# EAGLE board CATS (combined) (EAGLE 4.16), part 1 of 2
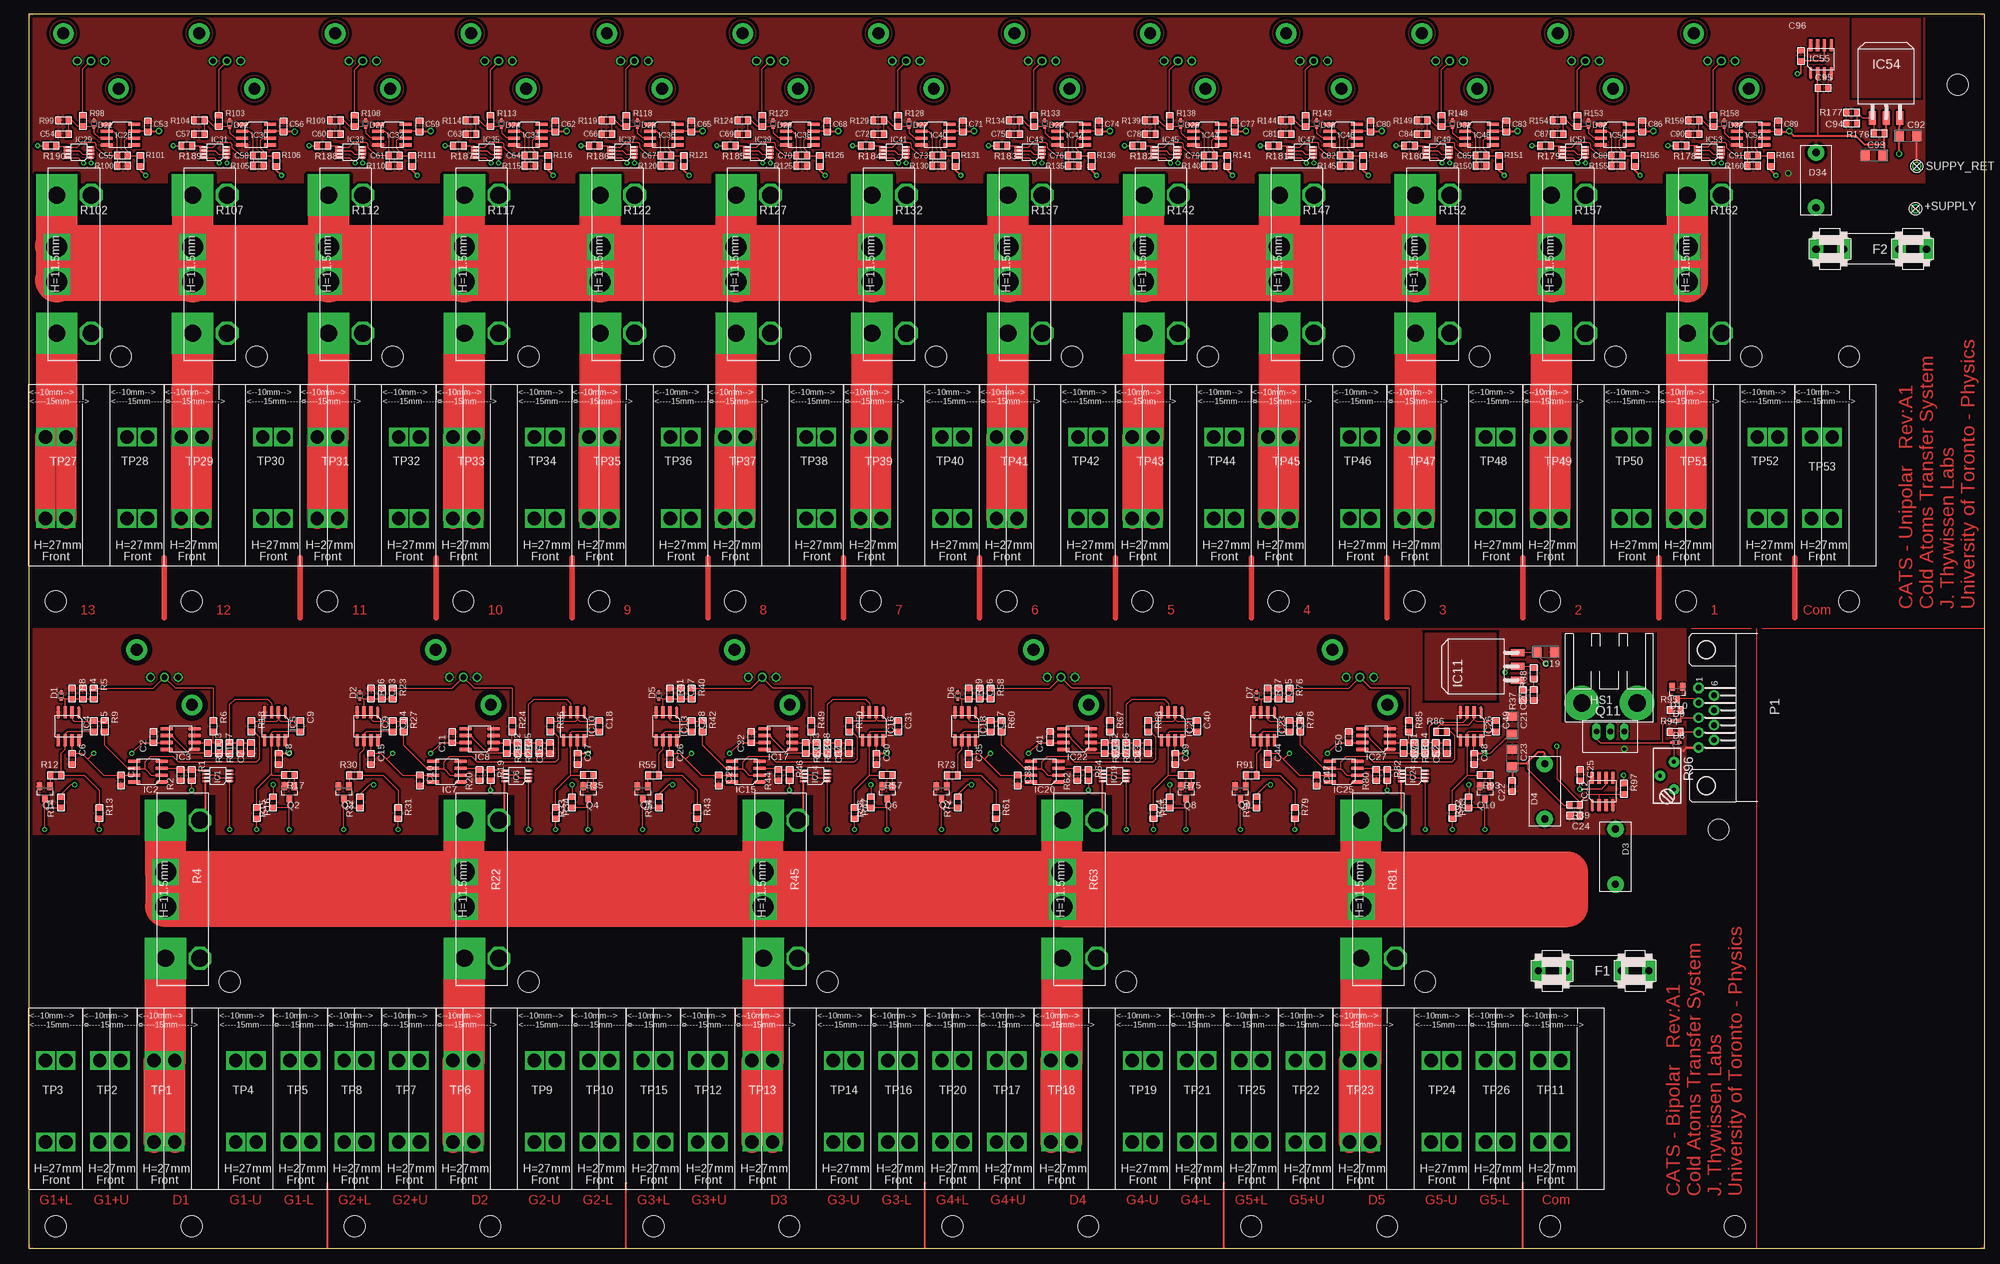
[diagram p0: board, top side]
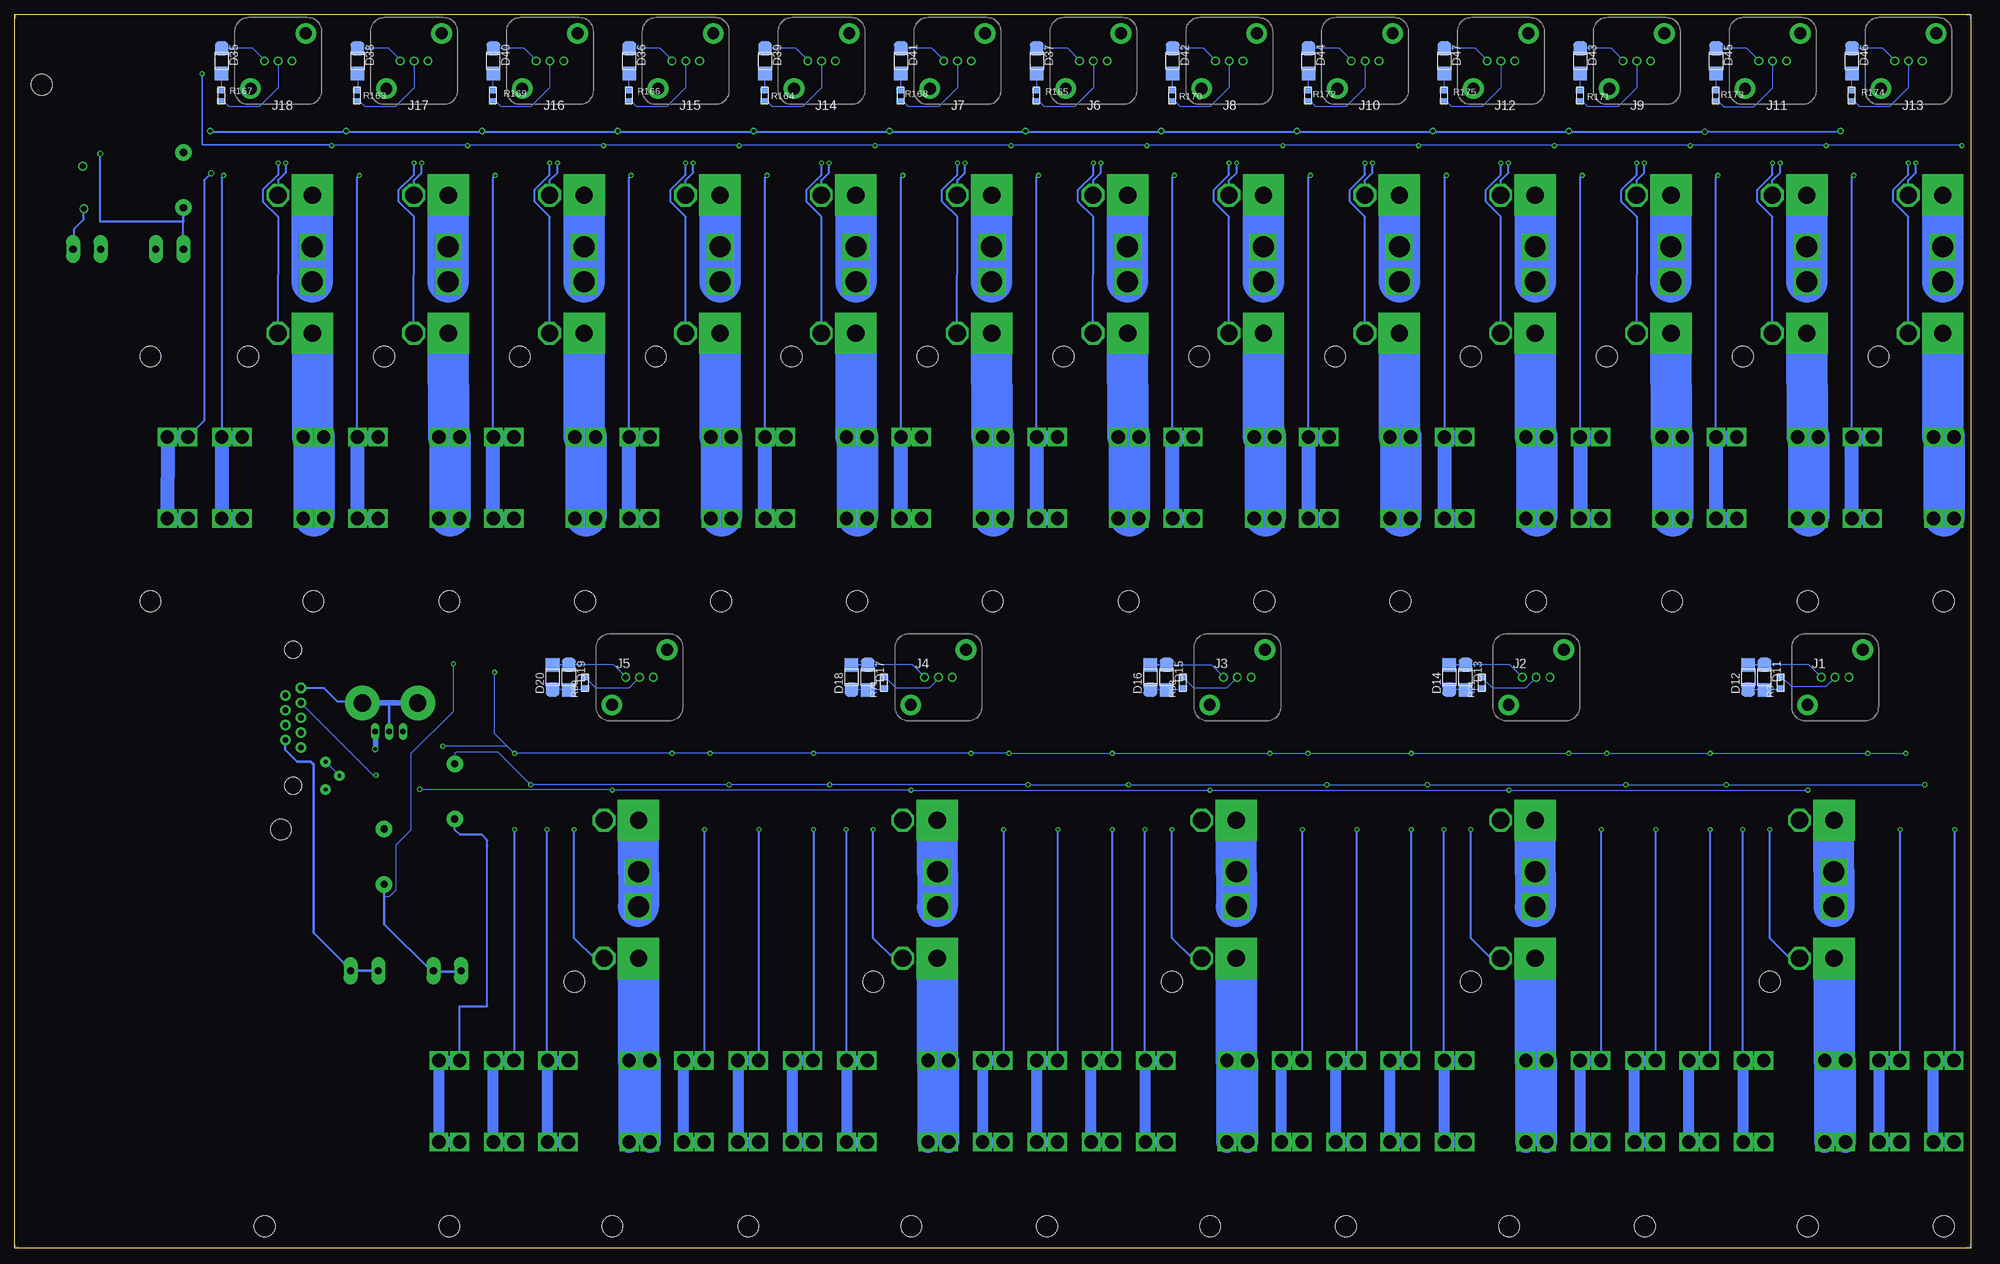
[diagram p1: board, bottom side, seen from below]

Size 360 x 227 mm. Coordinates in mm from the lower left corner, seen from the top.
Outline: 0,0 360,0 360,227 0,227 0,0
Copper layers (1*16): Top 0.035mm / dielectric 1.5mm / Bottom 0.035mm
Design rules "DRC standard check (7mil trace and gap, 20mil drill, etc)": minimum track width 7mil, minimum drill 20mil, track to track 7mil, track to pad 7mil, pad to pad 7mil, via to via 7mil, smd to smd 7mil, copper to edge 25mil, drill to drill 8mil, minimum pad ring 10mil, minimum via ring 8mil, stop-mask expansion 4mil, vias tented up to drill 0mil, thermal gap 10mil
Net classes: 0 default: clearance 0.406 mm; 1 Power: width 1.016 mm, drill 0.178 mm, clearance 3.175 mm
Holes 3.86 mm at 5,4 30,4 60,4 85,4 115,4 140,4 170,4 195,4 225,4 250,4 280,4 314,4 311,77 37,49 92,49 147,49 202,49 257,49 5,119 30,119 55,119 80,119 105,119 130,119 155,119 180,119 205,119 230,119 255,119 280,119 305,119 335,119 355,214 17,164 42,164 67,164 92,164 117,164 142,164 167,164 192,164 217,164 242,164 267,164 292,164 317,164 335,164
bKeepout: area 1.5,0.5 to 8.5,7.5; area 26.5,0.5 to 33.5,7.5; area 56.5,0.5 to 63.5,7.5; area 81.5,0.5 to 88.5,7.5; area 111.5,0.5 to 118.5,7.5; area 136.5,0.5 to 143.5,7.5; area 166.5,0.5 to 173.5,7.5; area 191.5,0.5 to 198.5,7.5; area 221.5,0.5 to 228.5,7.5; area 246.5,0.5 to 253.5,7.5; area 276.5,0.5 to 283.5,7.5; area 310.5,0.5 to 317.5,7.5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
tRestrict: 88 lines

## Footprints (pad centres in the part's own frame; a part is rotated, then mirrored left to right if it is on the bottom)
TP-0.042B = drill 1.067 round: TP 0,0
2012(0805) = smd 1.016 x 1.397: 1 -0.953,0; 2 0.953,0
EIA-A = smd 1.6 x 1.8: 1 -1.27,0; 2 1.905,0
SOD523 = smd 0.7 x 0.5: A 1.27,0; C 0,0
PASSIVE_0.4" = drill 1.321 pad 3.048 round: 1 -5.08,0; 2 5.08,0
SOT23 = smd 1 x 1.4: 1 -0.953,-0.953; 2 0.953,-0.953; 3 0,1.27
1209 = smd 2.5 x 2.5: A 2.3,0; K -2.3,0
FUSE = drill 1.321 pad 2.54 long: 1A -10.16,0; 1B -5.08,0; 2A 10.16,0; 2B 5.08,0
HEATSINK-5(TO-220) = drill 3.175 pad 6.35 round: 1 -5.08,0; 2 5.08,0
MSOP8 = smd 0.4 x 1.2: 1 -0.635,-1.905; 2 0,-1.905; 3 0.635,-1.905; 4 1.27,-1.905; 5 1.27,2.54; 6 0.635,2.54; 7 0,2.54; 8 -0.635,2.54
SOIC-8 = smd 0.6 x 2.2: 1 -1.27,-2.54; 2 0,-2.54; 3 1.27,-2.54; 4 2.54,-2.54; 5 2.54,2.54; 6 1.27,2.54; 7 0,2.54; 8 -1.27,2.54
TO263 = smd 1.27 x 2.54: 1 -2.54,0; 2 0,0; 3 2.54,0
CONN-BNC-AMP-TYPE1VERT = drill 1.067 round: CONDUCTOR 0,0; SHIELD1 -2.54,0; SHIELD2 2.54,0 | drill 2.184 pad 3.81 round: MTG1 -5.08,-5.08; MTG2 5.08,5.08
CONN-DB9-HORIZ1 = drill 1.067 pad 1.905 octagon: 1 -5.486,-1.422 | drill 1.067 pad 1.905 round: 2 -2.743,-1.422; 3 0,-1.422; 4 2.743,-1.422; 5 5.486,-1.422; 6 -4.115,1.422; 7 -1.372,1.422; 8 1.372,1.422; 9 4.115,1.422 | hole 3.175: -12.522,0; 12.522,0
TO220-VERTICAL = drill 1.067 long: 1 -2.54,0; 2 0,0; 3 2.54,0
OHMITE_650 = drill 3.175 pad 7.62 square: CURRENT1 -12.7,-3.81; CURRENT2 12.7,-3.81 | drill 3.175 octagon: SENSE1 -12.7,2.54; SENSE2 12.7,2.54
BOURNS-3296Y = drill 0.711 pad 1.905 round: CCW 2.54,1.27; CW -2.54,1.27; W 0,-1.27
PHEONIX_ZFKDS-10/15MM-TERMINAL-BLOCK = drill 2.438 square: T@1 -1.9,-7.5; T@2 1.9,-7.5; T@3 1.9,7.5; T@4 -1.9,7.5

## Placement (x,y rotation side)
+SUPPLY  [TP-0.042B]  347.25,191.2 90 top
C1  0.1uF  [2012(0805)]  17,86 270 top
C2  0.1uF  [2012(0805)]  23,94 90 top
C3  1nF  [2012(0805)]  33,92 270 top
C4  10nF  [2012(0805)]  10,102 270 top
C5  100pF  [2012(0805)]  12,96 270 top
C6  0.1uF  [2012(0805)]  8,90 270 top
C7  10nF  [2012(0805)]  41,92 90 top
C8  0.1uF  [2012(0805)]  46,90 270 top
C9  100pF  [2012(0805)]  50,96 270 top
C10  0.1uF  [2012(0805)]  72,86 270 top
C11  0.1uF  [2012(0805)]  78,94 90 top
C12  1nF  [2012(0805)]  88,92 270 top
C13  10nF  [2012(0805)]  65,102 270 top
C14  100pF  [2012(0805)]  67,96 270 top
C15  0.1uF  [2012(0805)]  63,90 270 top
C16  10nF  [2012(0805)]  96,92 90 top
C17  0.1uF  [2012(0805)]  101,90 270 top
C18  100pF  [2012(0805)]  105,96 270 top
C19  100uF/35V  [EIA-A]  279.5,109.65 180 top
C20  0.1uF  [2012(0805)]  277,101.75 90 top
C21  100uF/35V  [EIA-A]  273,96.5 270 top
C22  0.1uF  [2012(0805)]  273,85 90 top
C23  100uF/35V  [EIA-A]  273,90.5 270 top
C24  0.1uF  [2012(0805)]  284.5,79.5 180 top
C25  0.1uF  [2012(0805)]  285.5,87 270 top
C26  0.1uF  [2012(0805)]  118,90 270 top
C27  10nF  [2012(0805)]  120,102 270 top
C28  100pF  [2012(0805)]  122,96 270 top
C29  0.1uF  [2012(0805)]  127,86 270 top
C30  0.1uF  [2012(0805)]  156,90 270 top
C31  100pF  [2012(0805)]  160,96 270 top
C32  0.1uF  [2012(0805)]  133,94 90 top
C33  1nF  [2012(0805)]  143,92 270 top
C34  10nF  [2012(0805)]  151,92 90 top
C35  0.1uF  [2012(0805)]  173,90 270 top
C36  10nF  [2012(0805)]  175,102 270 top
C37  100pF  [2012(0805)]  177,96 270 top
C38  0.1uF  [2012(0805)]  182,86 270 top
C39  0.1uF  [2012(0805)]  211,90 270 top
C40  100pF  [2012(0805)]  215,96 270 top
C41  0.1uF  [2012(0805)]  188,94 90 top
C42  1nF  [2012(0805)]  198,92 270 top
C43  10nF  [2012(0805)]  206,92 90 top
C44  0.1uF  [2012(0805)]  228,90 270 top
C45  10nF  [2012(0805)]  230,102 270 top
C46  100pF  [2012(0805)]  232,96 270 top
C47  0.1uF  [2012(0805)]  237,86 270 top
C48  0.1uF  [2012(0805)]  266,90 270 top
C49  100pF  [2012(0805)]  270,96 270 top
C50  0.1uF  [2012(0805)]  243,94 90 top
C51  1nF  [2012(0805)]  253,92 270 top
C52  10nF  [2012(0805)]  261,92 90 top
C53  0.1uF  [2012(0805)]  21.97,206.35 90 top
C54  10nF  [2012(0805)]  6.43,204.95 0 top
C55  100pF  [2012(0805)]  17.27,201.01 0 top
C56  0.1uF  [2012(0805)]  46.97,206.35 90 top
C57  10nF  [2012(0805)]  31.43,204.95 0 top
C58  100pF  [2012(0805)]  42.27,201.01 0 top
C59  0.1uF  [2012(0805)]  71.97,206.35 90 top
C60  10nF  [2012(0805)]  56.43,204.95 0 top
C61  100pF  [2012(0805)]  67.27,201.01 0 top
C62  0.1uF  [2012(0805)]  96.97,206.35 90 top
C63  10nF  [2012(0805)]  81.43,204.95 0 top
C64  100pF  [2012(0805)]  92.27,201.01 0 top
C65  0.1uF  [2012(0805)]  121.97,206.35 90 top
C66  10nF  [2012(0805)]  106.43,204.95 0 top
C67  100pF  [2012(0805)]  117.27,201.01 0 top
C68  0.1uF  [2012(0805)]  146.97,206.35 90 top
C69  10nF  [2012(0805)]  131.43,204.95 0 top
C70  100pF  [2012(0805)]  142.27,201.01 0 top
C71  0.1uF  [2012(0805)]  171.97,206.35 90 top
C72  10nF  [2012(0805)]  156.43,204.95 0 top
C73  100pF  [2012(0805)]  167.27,201.01 0 top
C74  0.1uF  [2012(0805)]  196.97,206.35 90 top
C75  10nF  [2012(0805)]  181.43,204.95 0 top
C76  100pF  [2012(0805)]  192.27,201.01 0 top
C77  0.1uF  [2012(0805)]  221.97,206.35 90 top
C78  10nF  [2012(0805)]  206.43,204.95 0 top
C79  100pF  [2012(0805)]  217.27,201.01 0 top
C80  0.1uF  [2012(0805)]  246.97,206.35 90 top
C81  10nF  [2012(0805)]  231.43,204.95 0 top
C82  100pF  [2012(0805)]  242.27,201.01 0 top
C83  0.1uF  [2012(0805)]  271.97,206.35 90 top
C84  10nF  [2012(0805)]  256.43,204.95 0 top
C85  100pF  [2012(0805)]  267.27,201.01 0 top
C86  0.1uF  [2012(0805)]  296.97,206.35 90 top
C87  10nF  [2012(0805)]  281.43,204.95 0 top
C88  100pF  [2012(0805)]  292.27,201.01 0 top
C89  0.1uF  [2012(0805)]  321.97,206.35 90 top
C90  10nF  [2012(0805)]  306.43,204.95 0 top
C91  100pF  [2012(0805)]  317.27,201.01 0 top
C92  100uF/35V  [EIA-A]  346.14,204.6 180 top
C93  100uF/35V  [EIA-A]  339.28,201.04 0 top
C94  0.1uF  [2012(0805)]  335.47,206.88 0 top
C95  0.1uF  [2012(0805)]  330.22,213.42 0 top
C96  0.1uF  [2012(0805)]  326.14,219.33 270 top
D1  1N4148WT  [SOD523]  6,101 90 top
D2  1N4148WT  [SOD523]  61,101 90 top
D3  1N4750A  [PASSIVE_0.4"]  292,72 270 top
D4  1N4740A  [PASSIVE_0.4"]  279,84 90 top
D5  1N4148WT  [SOD523]  116,101 90 top
D6  1N4148WT  [SOD523]  171,101 90 top
D7  1N4148WT  [SOD523]  226,101 90 top
D8  1N4148WT  [SOD523]  302.5,93 0 top
D9  1N4148WT  [SOD523]  302.5,97 0 top
D10  BZX84-C5V1  [SOT23]  303.4,102.3 180 top
D11  SML-LXL1209UPGC  [1209]  38,105 270 bottom
D12  SML-LXL1209SOC  [1209]  41,105 90 bottom
D13  SML-LXL1209UPGC  [1209]  93,105 270 bottom
D14  SML-LXL1209SOC  [1209]  96,105 90 bottom
D15  SML-LXL1209UPGC  [1209]  148,105 270 bottom
D16  SML-LXL1209SOC  [1209]  151,105 90 bottom
D17  SML-LXL1209UPGC  [1209]  203,105 270 bottom
D18  SML-LXL1209SOC  [1209]  206,105 90 bottom
D19  SML-LXL1209UPGC  [1209]  258,105 270 bottom
D20  SML-LXL1209SOC  [1209]  261,105 90 bottom
D21  1N4148WT  [SOD523]  12.02,206.22 90 top
D22  1N4148WT  [SOD523]  37.02,206.22 90 top
D23  1N4148WT  [SOD523]  62.02,206.22 90 top
D24  1N4148WT  [SOD523]  87.02,206.22 90 top
D25  1N4148WT  [SOD523]  112.02,206.22 90 top
D26  1N4148WT  [SOD523]  137.02,206.22 90 top
D27  1N4148WT  [SOD523]  162.02,206.22 90 top
D28  1N4148WT  [SOD523]  187.02,206.22 90 top
D29  1N4148WT  [SOD523]  212.02,206.22 90 top
D30  1N4148WT  [SOD523]  237.02,206.22 90 top
D31  1N4148WT  [SOD523]  262.02,206.22 90 top
D32  1N4148WT  [SOD523]  287.02,206.22 90 top
D33  1N4148WT  [SOD523]  312.02,206.22 90 top
D34  1N4750A  [PASSIVE_0.4"]  328.93,196.47 270 top
D35  SML-LXL1209UPGC  [1209]  321.9,218.4 270 bottom
D36  SML-LXL1209UPGC  [1209]  246.9,218.4 270 bottom
D37  SML-LXL1209UPGC  [1209]  171.9,218.4 270 bottom
D38  SML-LXL1209UPGC  [1209]  296.9,218.4 270 bottom
D39  SML-LXL1209UPGC  [1209]  221.9,218.4 270 bottom
D40  SML-LXL1209UPGC  [1209]  271.9,218.4 270 bottom
D41  SML-LXL1209UPGC  [1209]  196.9,218.4 270 bottom
D42  SML-LXL1209UPGC  [1209]  146.9,218.4 270 bottom
D43  SML-LXL1209UPGC  [1209]  71.9,218.4 270 bottom
D44  SML-LXL1209UPGC  [1209]  121.9,218.4 270 bottom
D45  SML-LXL1209UPGC  [1209]  46.9,218.4 270 bottom
D46  SML-LXL1209UPGC  [1209]  21.9,218.4 270 bottom
D47  SML-LXL1209UPGC  [1209]  96.9,218.4 270 bottom
F1  0.1A-5x20  [FUSE]  288,51 180 top
F2  0.1A-5x20  [FUSE]  339.09,183.77 180 top
HS1  634-20ABP  [HEATSINK-5(TO-220)]  290.89,100.28 0 top
IC1  AD8212RMZ  [MSOP8]  35.15,86.54 90 top
IC2  AD820ARZ  [SOIC-8]  22,87 90 top
IC3  AD820ARZ  [SOIC-8]  28,93 90 top
IC4  AD820ARZ  [SOIC-8]  8,96 180 top
IC5  AD820ARZ  [SOIC-8]  46,96 180 top
IC6  AD8212RMZ  [MSOP8]  90.15,86.54 90 top
IC7  AD820ARZ  [SOIC-8]  77,87 90 top
IC8  AD820ARZ  [SOIC-8]  83,93 90 top
IC9  AD820ARZ  [SOIC-8]  63,96 180 top
IC10  AD820ARZ  [SOIC-8]  101,96 180 top
IC11  LM1086CS-ADJ  [TO263]  274,107 90 top
IC12  ADR435AR(Z)  [SOIC-8]  289,84 0 top
IC13  AD820ARZ  [SOIC-8]  118,96 180 top
IC14  AD8212RMZ  [MSOP8]  145.15,86.54 90 top
IC15  AD820ARZ  [SOIC-8]  132,87 90 top
IC16  AD820ARZ  [SOIC-8]  156,96 180 top
IC17  AD820ARZ  [SOIC-8]  138,93 90 top
IC18  AD820ARZ  [SOIC-8]  173,96 180 top
IC19  AD8212RMZ  [MSOP8]  200.15,86.54 90 top
IC20  AD820ARZ  [SOIC-8]  187,87 90 top
IC21  AD820ARZ  [SOIC-8]  211,96 180 top
IC22  AD820ARZ  [SOIC-8]  193,93 90 top
IC23  AD820ARZ  [SOIC-8]  228,96 180 top
IC24  AD8212RMZ  [MSOP8]  255.15,86.54 90 top
IC25  AD820ARZ  [SOIC-8]  242,87 90 top
IC26  AD820ARZ  [SOIC-8]  266,96 180 top
IC27  AD820ARZ  [SOIC-8]  248,93 90 top
IC28  AD820ARZ  [SOIC-8]  16.89,205.46 270 top
IC29  AD8212RMZ  [MSOP8]  9.61,201.27 90 top
IC30  AD820ARZ  [SOIC-8]  41.89,205.46 270 top
IC31  AD8212RMZ  [MSOP8]  34.6,201.27 90 top
IC32  AD820ARZ  [SOIC-8]  66.89,205.46 270 top
IC33  AD8212RMZ  [MSOP8]  59.6,201.27 90 top
IC34  AD820ARZ  [SOIC-8]  91.89,205.46 270 top
IC35  AD8212RMZ  [MSOP8]  84.61,201.27 90 top
IC36  AD820ARZ  [SOIC-8]  116.89,205.46 270 top
IC37  AD8212RMZ  [MSOP8]  109.61,201.27 90 top
IC38  AD820ARZ  [SOIC-8]  141.89,205.46 270 top
IC39  AD8212RMZ  [MSOP8]  134.6,201.27 90 top
IC40  AD820ARZ  [SOIC-8]  166.89,205.46 270 top
IC41  AD8212RMZ  [MSOP8]  159.6,201.27 90 top
IC42  AD820ARZ  [SOIC-8]  191.89,205.46 270 top
IC43  AD8212RMZ  [MSOP8]  184.6,201.27 90 top
IC44  AD820ARZ  [SOIC-8]  216.89,205.46 270 top
IC45  AD8212RMZ  [MSOP8]  209.6,201.27 90 top
IC46  AD820ARZ  [SOIC-8]  241.89,205.46 270 top
IC47  AD8212RMZ  [MSOP8]  234.6,201.27 90 top
IC48  AD820ARZ  [SOIC-8]  266.89,205.46 270 top
IC49  AD8212RMZ  [MSOP8]  259.61,201.27 90 top
IC50  AD820ARZ  [SOIC-8]  291.89,205.46 270 top
IC51  AD8212RMZ  [MSOP8]  284.61,201.27 90 top
IC52  AD820ARZ  [SOIC-8]  316.89,205.46 270 top
IC53  AD8212RMZ  [MSOP8]  309.61,201.27 90 top
IC54  LM1086CS-ADJ  [TO263]  341.82,207.9 0 top
IC55  ADR435AR(Z)  [SOIC-8]  329.18,218.69 0 top
J1  Amp 227673-1  [CONN-BNC-AMP-TYPE1VERT]  25,105 0 bottom
J2  Amp 227673-1  [CONN-BNC-AMP-TYPE1VERT]  80,105 0 bottom
J3  Amp 227673-1  [CONN-BNC-AMP-TYPE1VERT]  135,105 0 bottom
J4  Amp 227673-1  [CONN-BNC-AMP-TYPE1VERT]  190,105 0 bottom
J5  Amp 227673-1  [CONN-BNC-AMP-TYPE1VERT]  245,105 0 bottom
J6  Amp 227673-1  [CONN-BNC-AMP-TYPE1VERT]  161.49,218.38 0 bottom
J7  Amp 227673-1  [CONN-BNC-AMP-TYPE1VERT]  186.49,218.38 0 bottom
J8  Amp 227673-1  [CONN-BNC-AMP-TYPE1VERT]  136.49,218.38 0 bottom
J9  Amp 227673-1  [CONN-BNC-AMP-TYPE1VERT]  61.49,218.38 0 bottom
J10  Amp 227673-1  [CONN-BNC-AMP-TYPE1VERT]  111.49,218.38 0 bottom
J11  Amp 227673-1  [CONN-BNC-AMP-TYPE1VERT]  36.49,218.38 0 bottom
J12  Amp 227673-1  [CONN-BNC-AMP-TYPE1VERT]  86.49,218.38 0 bottom
J13  Amp 227673-1  [CONN-BNC-AMP-TYPE1VERT]  11.49,218.38 0 bottom
J14  Amp 227673-1  [CONN-BNC-AMP-TYPE1VERT]  211.49,218.38 0 bottom
J15  Amp 227673-1  [CONN-BNC-AMP-TYPE1VERT]  236.49,218.38 0 bottom
J16  Amp 227673-1  [CONN-BNC-AMP-TYPE1VERT]  261.49,218.38 0 bottom
J17  Amp 227673-1  [CONN-BNC-AMP-TYPE1VERT]  286.49,218.38 0 bottom
J18  Amp 227673-1  [CONN-BNC-AMP-TYPE1VERT]  311.49,218.38 0 bottom
P1  [CONN-DB9-HORIZ1]  308.74,97.57 270 top
Q1  MMBT5551  [SOT23]  3,84 180 top
Q2  MMBT5551  [SOT23]  48,84 180 top
Q3  MMBT5551  [SOT23]  58,84 180 top
Q4  MMBT5551  [SOT23]  103,84 180 top
Q5  MMBT5551  [SOT23]  113,84 180 top
Q6  MMBT5551  [SOT23]  158,84 180 top
Q7  MMBT5551  [SOT23]  168,84 180 top
Q8  MMBT5551  [SOT23]  213,84 180 top
Q9  MMBT5551  [SOT23]  223,84 180 top
Q10  MMBT5551  [SOT23]  268,84 180 top
Q11  NDP6060L  [TO220-VERTICAL]  291.08,95.04 0 top
R1  75K  [2012(0805)]  30,87 270 top
R2  3.92K  [2012(0805)]  28,87 90 top
R3  3.01K  [2012(0805)]  35,104 90 bottom
R4  2mOhm/5W  [OHMITE_650]  29,66 270 top
R5  9.09K  [2012(0805)]  12,102 270 top
R6  10K  [2012(0805)]  34,96 270 top
R7  10K  [2012(0805)]  35,92 270 top
R8  1K  [2012(0805)]  8,102 270 top
R9  3.92K  [2012(0805)]  14,96 270 top
R10  9.09K  [2012(0805)]  37,92 90 top
R11  1K  [2012(0805)]  39,92 90 top
R12  10K  [2012(0805)]  5,87 0 top
R13  100  [2012(0805)]  13,80 270 top
R14  2K  [2012(0805)]  6,82 90 top
R15  2K  [2012(0805)]  45,82 90 top
R16  100  [2012(0805)]  42,80 270 top
R17  10K  [2012(0805)]  48,87 180 top
R18  3.92K  [2012(0805)]  41,96 270 top
R19  75K  [2012(0805)]  85,87 270 top
R20  3.92K  [2012(0805)]  83,87 90 top
R21  3.01K  [2012(0805)]  90,104 90 bottom
R22  2mOhm/5W  [OHMITE_650]  84,66 270 top
R23  9.09K  [2012(0805)]  67,102 270 top
R24  10K  [2012(0805)]  89,96 270 top
R25  10K  [2012(0805)]  90,92 270 top
R26  1K  [2012(0805)]  63,102 270 top
R27  3.92K  [2012(0805)]  69,96 270 top
R28  9.09K  [2012(0805)]  92,92 90 top
R29  1K  [2012(0805)]  94,92 90 top
R30  10K  [2012(0805)]  60,87 0 top
R31  100  [2012(0805)]  68,80 270 top
R32  2K  [2012(0805)]  61,82 90 top
R33  2K  [2012(0805)]  100,82 90 top
R34  100  [2012(0805)]  97,80 270 top
R35  10K  [2012(0805)]  103,87 180 top
R36  3.92K  [2012(0805)]  96,96 270 top
R37  1.47K  [2012(0805)]  275,101.75 90 top
R38  124  [2012(0805)]  277,105.75 90 top
R39  301  [2012(0805)]  284.5,81.5 180 top
R40  9.09K  [2012(0805)]  122,102 270 top
R41  1K  [2012(0805)]  118,102 270 top
R42  3.92K  [2012(0805)]  124,96 270 top
R43  100  [2012(0805)]  123,80 270 top
R44  3.92K  [2012(0805)]  138,87 90 top
R45  2mOhm/5W  [OHMITE_650]  139,66 270 top
R46  75K  [2012(0805)]  140,87 270 top
R47  100  [2012(0805)]  152,80 270 top
R48  10K  [2012(0805)]  145,92 270 top
R49  10K  [2012(0805)]  144,96 270 top
R50  3.92K  [2012(0805)]  151,96 270 top
R51  9.09K  [2012(0805)]  147,92 90 top
R52  1K  [2012(0805)]  149,92 90 top
R53  3.01K  [2012(0805)]  145,104 90 bottom
R54  2K  [2012(0805)]  116,82 90 top
R55  10K  [2012(0805)]  115,87 0 top
R56  2K  [2012(0805)]  155,82 90 top
R57  10K  [2012(0805)]  158,87 180 top
R58  9.09K  [2012(0805)]  177,102 270 top
R59  1K  [2012(0805)]  173,102 270 top
R60  3.92K  [2012(0805)]  179,96 270 top
R61  100  [2012(0805)]  178,80 270 top
R62  3.92K  [2012(0805)]  193,87 90 top
R63  2mOhm/5W  [OHMITE_650]  194,66 270 top
R64  75K  [2012(0805)]  195,87 270 top
R65  100  [2012(0805)]  207,80 270 top
R66  10K  [2012(0805)]  200,92 270 top
R67  10K  [2012(0805)]  199,96 270 top
R68  3.92K  [2012(0805)]  206,96 270 top
R69  9.09K  [2012(0805)]  202,92 90 top
R70  1K  [2012(0805)]  204,92 90 top
R71  3.01K  [2012(0805)]  200,104 90 bottom
R72  2K  [2012(0805)]  171,82 90 top
R73  10K  [2012(0805)]  170,87 0 top
R74  2K  [2012(0805)]  210,82 90 top
R75  10K  [2012(0805)]  213,87 180 top
R76  9.09K  [2012(0805)]  232,102 270 top
R77  1K  [2012(0805)]  228,102 270 top
R78  3.92K  [2012(0805)]  234,96 270 top
R79  100  [2012(0805)]  233,80 270 top
R80  3.92K  [2012(0805)]  248,87 90 top
R81  2mOhm/5W  [OHMITE_650]  249,66 270 top
R82  75K  [2012(0805)]  250,87 270 top
R83  100  [2012(0805)]  262,80 270 top
R84  10K  [2012(0805)]  255,92 270 top
R85  10K  [2012(0805)]  254,96 270 top
R86  3.92K  [2012(0805)]  260,95 0 top
R87  9.09K  [2012(0805)]  257,92 90 top
R88  1K  [2012(0805)]  259,92 90 top
R89  3.01K  [2012(0805)]  255,104 90 bottom
R90  2K  [2012(0805)]  226,82 90 top
R91  10K  [2012(0805)]  225,87 0 top
R92  2K  [2012(0805)]  265,82 90 top
R93  10K  [2012(0805)]  268,87 180 top
R94  ???  [2012(0805)]  303,95 0 top
R95  ???  [2012(0805)]  303,99 0 top
R96  3296Y-10K  [BOURNS-3296Y]  301.5,86.9 270 top
R97  1K  [2012(0805)]  293.55,84.5 270 top
R98  9.09K  [2012(0805)]  9.99,207.36 270 top
R99  1K  [2012(0805)]  6.43,207.49 0 top
R100  3.92K  [2012(0805)]  17.27,199.11 180 top
R101  100  [2012(0805)]  20.57,200 270 top
R102  2mOhm/5W  [OHMITE_650]  9,181 270 top
R103  9.09K  [2012(0805)]  34.99,207.36 270 top
R104  1K  [2012(0805)]  31.43,207.49 0 top
R105  3.92K  [2012(0805)]  42.27,199.11 180 top
R106  100  [2012(0805)]  45.57,200 270 top
R107  2mOhm/5W  [OHMITE_650]  34,181 270 top
R108  9.09K  [2012(0805)]  59.99,207.36 270 top
R109  1K  [2012(0805)]  56.43,207.49 0 top
R110  3.92K  [2012(0805)]  67.27,199.11 180 top
R111  100  [2012(0805)]  70.57,200 270 top
R112  2mOhm/5W  [OHMITE_650]  59,181 270 top
R113  9.09K  [2012(0805)]  84.99,207.36 270 top
R114  1K  [2012(0805)]  81.43,207.49 0 top
R115  3.92K  [2012(0805)]  92.27,199.11 180 top
R116  100  [2012(0805)]  95.57,200 270 top
R117  2mOhm/5W  [OHMITE_650]  84,181 270 top
R118  9.09K  [2012(0805)]  109.99,207.36 270 top
R119  1K  [2012(0805)]  106.43,207.49 0 top
R120  3.92K  [2012(0805)]  117.27,199.11 180 top
R121  100  [2012(0805)]  120.57,200 270 top
R122  2mOhm/5W  [OHMITE_650]  109,181 270 top
R123  9.09K  [2012(0805)]  134.99,207.36 270 top
R124  1K  [2012(0805)]  131.43,207.49 0 top
R125  3.92K  [2012(0805)]  142.27,199.11 180 top
R126  100  [2012(0805)]  145.57,200 270 top
R127  2mOhm/5W  [OHMITE_650]  134,181 270 top
R128  9.09K  [2012(0805)]  159.99,207.36 270 top
R129  1K  [2012(0805)]  156.43,207.49 0 top
R130  3.92K  [2012(0805)]  167.27,199.11 180 top
R131  100  [2012(0805)]  170.57,200 270 top
R132  2mOhm/5W  [OHMITE_650]  159,181 270 top
R133  9.09K  [2012(0805)]  184.99,207.36 270 top
R134  1K  [2012(0805)]  181.43,207.49 0 top
R135  3.92K  [2012(0805)]  192.27,199.11 180 top
R136  100  [2012(0805)]  195.57,200 270 top
R137  2mOhm/5W  [OHMITE_650]  184,181 270 top
R138  9.09K  [2012(0805)]  209.99,207.36 270 top
R139  1K  [2012(0805)]  206.43,207.49 0 top
R140  3.92K  [2012(0805)]  217.27,199.11 180 top
R141  100  [2012(0805)]  220.57,200 270 top
R142  2mOhm/5W  [OHMITE_650]  209,181 270 top
R143  9.09K  [2012(0805)]  234.99,207.36 270 top
R144  1K  [2012(0805)]  231.43,207.49 0 top
R145  3.92K  [2012(0805)]  242.27,199.11 180 top
R146  100  [2012(0805)]  245.57,200 270 top
R147  2mOhm/5W  [OHMITE_650]  234,181 270 top
R148  9.09K  [2012(0805)]  259.99,207.36 270 top
R149  1K  [2012(0805)]  256.43,207.49 0 top
R150  3.92K  [2012(0805)]  267.27,199.11 180 top
R151  100  [2012(0805)]  270.57,200 270 top
R152  2mOhm/5W  [OHMITE_650]  259,181 270 top
R153  9.09K  [2012(0805)]  284.99,207.36 270 top
R154  1K  [2012(0805)]  281.43,207.49 0 top
R155  3.92K  [2012(0805)]  292.27,199.11 180 top
R156  100  [2012(0805)]  295.57,200 270 top
R157  2mOhm/5W  [OHMITE_650]  284,181 270 top
R158  9.09K  [2012(0805)]  309.99,207.36 270 top
R159  1K  [2012(0805)]  306.43,207.49 0 top
R160  3.92K  [2012(0805)]  317.27,199.11 180 top
R161  100  [2012(0805)]  320.57,200 270 top
R162  2mOhm/5W  [OHMITE_650]  309,181 270 top
R163  3.01K  [2012(0805)]  297,212 270 bottom
R164  3.01K  [2012(0805)]  222,212 270 bottom
R165  3.01K  [2012(0805)]  172,212 270 bottom
R166  3.01K  [2012(0805)]  247,212 270 bottom
R167  3.01K  [2012(0805)]  322,212 270 bottom
R168  3.01K  [2012(0805)]  197,212 270 bottom
R169  3.01K  [2012(0805)]  272,212 270 bottom
R170  3.01K  [2012(0805)]  147,212 270 bottom
R171  3.01K  [2012(0805)]  72,212 270 bottom
R172  3.01K  [2012(0805)]  122,212 270 bottom
R173  3.01K  [2012(0805)]  47,212 270 bottom
R174  3.01K  [2012(0805)]  22,212 270 bottom
R175  3.01K  [2012(0805)]  97,212 270 bottom
R176  124  [2012(0805)]  340.55,205.11 0 top
R177  1.47K  [2012(0805)]  335.47,208.92 0 top
R178  75K  [2012(0805)]  304.12,202.76 180 top
R179  75K  [2012(0805)]  279.12,202.76 180 top
R180  75K  [2012(0805)]  254.12,202.76 180 top
R181  75K  [2012(0805)]  229.12,202.76 180 top
R182  75K  [2012(0805)]  204.12,202.76 180 top
R183  75K  [2012(0805)]  179.12,202.76 180 top
R184  75K  [2012(0805)]  154.12,202.76 180 top
R185  75K  [2012(0805)]  129.12,202.76 180 top
R186  75K  [2012(0805)]  104.12,202.76 180 top
R187  75K  [2012(0805)]  79.12,202.76 180 top
R188  75K  [2012(0805)]  54.12,202.76 180 top
R189  75K  [2012(0805)]  29.12,202.76 180 top
R190  75K  [2012(0805)]  4.12,202.76 180 top
SUPPY_RET  [TP-0.042B]  347.44,199.01 270 top
TP1  Pheonix-1987631  [PHEONIX_ZFKDS-10/15MM-TERMINAL-BLOCK]  25,27 0 top
TP2  Pheonix-1987628  [PHEONIX_ZFKDS-10/15MM-TERMINAL-BLOCK]  15,27 0 top
TP3  Pheonix-1987628  [PHEONIX_ZFKDS-10/15MM-TERMINAL-BLOCK]  5,27 0 top
TP4  Pheonix-1987628  [PHEONIX_ZFKDS-10/15MM-TERMINAL-BLOCK]  40,27 0 top
TP5  Pheonix-1987628  [PHEONIX_ZFKDS-10/15MM-TERMINAL-BLOCK]  50,27 0 top
TP6  Pheonix-1987631  [PHEONIX_ZFKDS-10/15MM-TERMINAL-BLOCK]  80,27 0 top
TP7  Pheonix-1987628  [PHEONIX_ZFKDS-10/15MM-TERMINAL-BLOCK]  70,27 0 top
TP8  Pheonix-1987628  [PHEONIX_ZFKDS-10/15MM-TERMINAL-BLOCK]  60,27 0 top
TP9  Pheonix-1987628  [PHEONIX_ZFKDS-10/15MM-TERMINAL-BLOCK]  95,27 0 top
TP10  Pheonix-1987628  [PHEONIX_ZFKDS-10/15MM-TERMINAL-BLOCK]  105,27 0 top
TP11  Pheonix-1987628  [PHEONIX_ZFKDS-10/15MM-TERMINAL-BLOCK]  280,27 0 top
TP12  Pheonix-1987628  [PHEONIX_ZFKDS-10/15MM-TERMINAL-BLOCK]  125,27 0 top
TP13  Pheonix-1987631  [PHEONIX_ZFKDS-10/15MM-TERMINAL-BLOCK]  135,27 0 top
TP14  Pheonix-1987628  [PHEONIX_ZFKDS-10/15MM-TERMINAL-BLOCK]  150,27 0 top
TP15  Pheonix-1987628  [PHEONIX_ZFKDS-10/15MM-TERMINAL-BLOCK]  115,27 0 top
TP16  Pheonix-1987628  [PHEONIX_ZFKDS-10/15MM-TERMINAL-BLOCK]  160,27 0 top
TP17  Pheonix-1987628  [PHEONIX_ZFKDS-10/15MM-TERMINAL-BLOCK]  180,27 0 top
TP18  Pheonix-1987631  [PHEONIX_ZFKDS-10/15MM-TERMINAL-BLOCK]  190,27 0 top
TP19  Pheonix-1987628  [PHEONIX_ZFKDS-10/15MM-TERMINAL-BLOCK]  205,27 0 top
TP20  Pheonix-1987628  [PHEONIX_ZFKDS-10/15MM-TERMINAL-BLOCK]  170,27 0 top
TP21  Pheonix-1987628  [PHEONIX_ZFKDS-10/15MM-TERMINAL-BLOCK]  215,27 0 top
TP22  Pheonix-1987628  [PHEONIX_ZFKDS-10/15MM-TERMINAL-BLOCK]  235,27 0 top
TP23  Pheonix-1987631  [PHEONIX_ZFKDS-10/15MM-TERMINAL-BLOCK]  245,27 0 top
TP24  Pheonix-1987628  [PHEONIX_ZFKDS-10/15MM-TERMINAL-BLOCK]  260,27 0 top
TP25  Pheonix-1987628  [PHEONIX_ZFKDS-10/15MM-TERMINAL-BLOCK]  225,27 0 top
TP26  Pheonix-1987628  [PHEONIX_ZFKDS-10/15MM-TERMINAL-BLOCK]  270,27 0 top
TP27  Pheonix-1987631  [PHEONIX_ZFKDS-10/15MM-TERMINAL-BLOCK]  5,141.7 0 top
TP28  Pheonix-1987628  [PHEONIX_ZFKDS-10/15MM-TERMINAL-BLOCK]  20,141.7 0 top
TP29  Pheonix-1987631  [PHEONIX_ZFKDS-10/15MM-TERMINAL-BLOCK]  30,141.7 0 top
TP30  Pheonix-1987628  [PHEONIX_ZFKDS-10/15MM-TERMINAL-BLOCK]  45,141.7 0 top
TP31  Pheonix-1987631  [PHEONIX_ZFKDS-10/15MM-TERMINAL-BLOCK]  55,141.7 0 top
TP32  Pheonix-1987628  [PHEONIX_ZFKDS-10/15MM-TERMINAL-BLOCK]  70,141.7 0 top
TP33  Pheonix-1987631  [PHEONIX_ZFKDS-10/15MM-TERMINAL-BLOCK]  80,141.7 0 top
TP34  Pheonix-1987628  [PHEONIX_ZFKDS-10/15MM-TERMINAL-BLOCK]  95,141.7 0 top
TP35  Pheonix-1987631  [PHEONIX_ZFKDS-10/15MM-TERMINAL-BLOCK]  105,141.7 0 top
TP36  Pheonix-1987628  [PHEONIX_ZFKDS-10/15MM-TERMINAL-BLOCK]  120,141.7 0 top
TP37  Pheonix-1987631  [PHEONIX_ZFKDS-10/15MM-TERMINAL-BLOCK]  130,141.7 0 top
TP38  Pheonix-1987628  [PHEONIX_ZFKDS-10/15MM-TERMINAL-BLOCK]  145,141.7 0 top
TP39  Pheonix-1987631  [PHEONIX_ZFKDS-10/15MM-TERMINAL-BLOCK]  155,141.7 0 top
TP40  Pheonix-1987628  [PHEONIX_ZFKDS-10/15MM-TERMINAL-BLOCK]  170,141.7 0 top
TP41  Pheonix-1987631  [PHEONIX_ZFKDS-10/15MM-TERMINAL-BLOCK]  180,141.7 0 top
TP42  Pheonix-1987628  [PHEONIX_ZFKDS-10/15MM-TERMINAL-BLOCK]  195,141.7 0 top
TP43  Pheonix-1987631  [PHEONIX_ZFKDS-10/15MM-TERMINAL-BLOCK]  205,141.7 0 top
TP44  Pheonix-1987628  [PHEONIX_ZFKDS-10/15MM-TERMINAL-BLOCK]  220,141.7 0 top
TP45  Pheonix-1987631  [PHEONIX_ZFKDS-10/15MM-TERMINAL-BLOCK]  230,141.7 0 top
TP46  Pheonix-1987628  [PHEONIX_ZFKDS-10/15MM-TERMINAL-BLOCK]  245,141.7 0 top
TP47  Pheonix-1987631  [PHEONIX_ZFKDS-10/15MM-TERMINAL-BLOCK]  255,141.7 0 top
TP48  Pheonix-1987628  [PHEONIX_ZFKDS-10/15MM-TERMINAL-BLOCK]  270,141.7 0 top
TP49  Pheonix-1987631  [PHEONIX_ZFKDS-10/15MM-TERMINAL-BLOCK]  280,141.7 0 top
TP50  Pheonix-1987628  [PHEONIX_ZFKDS-10/15MM-TERMINAL-BLOCK]  295,141.7 0 top
TP51  Pheonix-1987631  [PHEONIX_ZFKDS-10/15MM-TERMINAL-BLOCK]  305,141.7 0 top
TP52  Pheonix-1987628  [PHEONIX_ZFKDS-10/15MM-TERMINAL-BLOCK]  320,141.7 0 top
TP53  Pheonix-1987628  [PHEONIX_ZFKDS-10/15MM-TERMINAL-BLOCK]  330,141.7 0 top
U$106  [TITLEBLOCK_PCB]  not placed on the board

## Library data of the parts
+SUPPLY C1-C96 D1-D47 F1 F2 HS1 IC1-IC55 J1-J18 P1 Q1-Q11 R1-R190 SUPPY_RET TP1-TP53 U$106 = QuantumOptics

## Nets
+5.0V: C25.2 IC12.6 R1.2 R19.2 R46.2 R64.2 R82.2
+5.0V1: C96.2 IC55.6 R178.2 R179.2 R180.2 R181.2 R182.2 R183.2 R184.2 R185.2 R186.2 R187.2 R188.2 R189.2 R190.2
+10V: C22.2 C23.2 D4.2 R14.2 R15.2 R32.2 R33.2 R39.2 R54.2 R56.2 R72.2 R74.2 R90.2 R92.2
+16V: C53.1 C56.1 C59.1 C62.1 C65.1 C68.1 C71.1 C74.1 C77.1 C80.1 C83.1 C86.1 C89.1 C93.2 C95.1 IC28.7 IC30.7 IC32.7 IC34.7 IC36.7 IC38.7 IC40.7 IC42.7 IC44.7 IC46.7 IC48.7 IC50.7 IC52.7 IC54.2 IC55.2 R176.2
+16V1: C1.1 C2.1 C6.1 C8.1 C10.1 C11.1 C15.1 C17.1 C21.2 C24.1 C26.1 C29.1 C30.1 C32.1 C35.1 C38.1 C39.1 C41.1 C44.1 C47.1 C48.1 C50.1 IC2.7 IC3.7 IC4.7 IC5.7 IC7.7 IC8.7 IC9.7 IC10.7 IC11.2 IC12.2 IC13.7 IC15.7 IC16.7 IC17.7 IC18.7 IC20.7 IC21.7 IC22.7 IC23.7 IC25.7 IC26.7 IC27.7 R38.2 R39.1 R97.2
+V-COIL [Power]: R102.CURRENT1 R107.CURRENT1 R112.CURRENT1 R117.CURRENT1 R122.CURRENT1 R127.CURRENT1 R132.CURRENT1 R137.CURRENT1 R142.CURRENT1 R147.CURRENT1 R152.CURRENT1 R157.CURRENT1 R162.CURRENT1
+V-COIL1 [Power]: R4.CURRENT1 R22.CURRENT1 R45.CURRENT1 R63.CURRENT1 R81.CURRENT1
AGND: C53.2 C54.1 C56.2 C57.1 C59.2 C60.1 C62.2 C63.1 C65.2 C66.1 C68.2 C69.1 C71.2 C72.1 C74.2 C75.1 C77.2 C78.1 C80.2 C81.1 C83.2 C84.1 C86.2 C87.1 C89.2 C90.1 C92.1 C93.1 C94.1 C95.2 C96.1 D21.A D22.A D23.A D24.A D25.A D26.A D27.A D28.A D29.A D30.A D31.A D32.A D33.A D34.1 D35.K D36.K D37.K D38.K D39.K D40.K D41.K D42.K D43.K D44.K D45.K D46.K D47.K IC28.4 IC29.3 IC30.4 IC31.3 IC32.4 IC33.3 IC34.4 IC35.3 IC36.4 IC37.3 IC38.4 IC39.3 IC40.4 IC41.3 IC42.4 IC43.3 IC44.4 IC45.3 IC46.4 IC47.3 IC48.4 IC49.3 IC50.4 IC51.3 IC52.4 IC53.3 IC55.4 J6.SHIELD1 J6.SHIELD2 J7.SHIELD1 J7.SHIELD2 J8.SHIELD1 J8.SHIELD2 J9.SHIELD1 J9.SHIELD2 J10.SHIELD1 J10.SHIELD2 J11.SHIELD1 J11.SHIELD2 J12.SHIELD1 J12.SHIELD2 J13.SHIELD1 J13.SHIELD2 J14.SHIELD1 J14.SHIELD2 J15.SHIELD1 J15.SHIELD2 J16.SHIELD1 J16.SHIELD2 J17.SHIELD1 J17.SHIELD2 J18.SHIELD1 J18.SHIELD2 R99.1 R100.1 R104.1 R105.1 R109.1 R110.1 R114.1 R115.1 R119.1 R120.1 R124.1 R125.1 R129.1 R130.1 R134.1 R135.1 R139.1 R140.1 R144.1 R145.1 R149.1 R150.1 R154.1 R155.1 R159.1 R160.1 R177.1 SUPPY_RET.TP TP53.T@1 TP53.T@2 TP53.T@3 TP53.T@4
AGND1: C1.2 C2.2 C4.1 C6.2 C7.1 C8.2 C10.2 C11.2 C13.1 C15.2 C16.1 C17.2 C19.1 C20.1 C21.1 C22.1 C23.1 C24.2 C25.1 C26.2 C27.1 C29.2 C30.2 C32.2 C34.1 C35.2 C36.1 C38.2 C39.2 C41.2 C43.1 C44.2 C45.1 C47.2 C48.2 C50.2 C52.1 D1.A D2.A D3.1 D4.1 D5.A D6.A D7.A D10.1 D11.K D12.A D13.K D14.A D15.K D16.A D17.K D18.A D19.K D20.A IC1.3 IC2.4 IC3.3 IC3.4 IC4.4 IC5.4 IC6.3 IC7.4 IC8.3 IC8.4 IC9.4 IC10.4 IC12.4 IC13.4 IC14.3 IC15.4 IC16.4 IC17.3 IC17.4 IC18.4 IC19.3 IC20.4 IC21.4 IC22.3 IC22.4 IC23.4 IC24.3 IC25.4 IC26.4 IC27.3 IC27.4 J1.SHIELD1 J1.SHIELD2 J2.SHIELD1 J2.SHIELD2 J3.SHIELD1 J3.SHIELD2 J4.SHIELD1 J4.SHIELD2 J5.SHIELD1 J5.SHIELD2 P1.5 Q1.2 Q2.2 Q3.2 Q4.2 Q5.2 Q6.2 Q7.2 Q8.2 Q9.2 Q10.2 Q11.3 R2.1 R8.1 R11.1 R20.1 R26.1 R29.1 R37.1 R41.1 R44.1 R52.1 R59.1 R62.1 R70.1 R77.1 R80.1 R88.1 R94.1 R95.1 R96.CCW TP11.T@1 TP11.T@2 TP11.T@3 TP11.T@4
N$1: IC1.5 IC2.3 R1.1 R2.2
N$2: IC2.2 IC2.6 R9.2 R18.2
N$3: IC1.1 R4.SENSE2
N$4: IC1.8 R4.SENSE1
N$5: IC1.2 IC1.6
N$6: J1.CONDUCTOR R3.2 R5.1 R6.1
N$7: C9.1 IC5.2 R18.1
N$8 [Power]: R4.CURRENT2 TP1.T@1 TP1.T@2 TP1.T@3 TP1.T@4
N$9: C9.2 IC5.6 R16.1 R17.2
N$10: R16.2 TP4.T@1 TP4.T@2 TP4.T@3 TP4.T@4
N$11: C3.2 IC3.6 R7.2 R10.1
N$12: C3.1 IC3.2 R6.2 R7.1
N$13: C7.2 IC5.3 R10.2 R11.2
N$14: Q1.3 R14.1 TP3.T@1 TP3.T@2 TP3.T@3 TP3.T@4
N$15: Q1.1 R12.1
N$16: C13.2 D2.C IC9.3 R23.2 R26.2
N$17: Q2.3 R15.1 TP5.T@1 TP5.T@2 TP5.T@3 TP5.T@4
N$18: Q2.1 R17.1
N$19: C14.1 IC9.2 R27.1
N$20: C14.2 IC9.6 R30.2 R31.1
N$21: R31.2 TP7.T@1 TP7.T@2 TP7.T@3 TP7.T@4
N$22: D13.A D14.K R21.1
N$23: IC6.1 R22.SENSE2
N$24: IC6.8 R22.SENSE1
N$25: IC6.2 IC6.6
N$26 [Power]: R22.CURRENT2 TP6.T@1 TP6.T@2 TP6.T@3 TP6.T@4
N$27: IC6.5 IC7.3 R19.1 R20.2
N$28: IC7.2 IC7.6 R27.2 R36.2
N$29: C18.1 IC10.2 R36.1
N$30: C18.2 IC10.6 R34.1 R35.2
N$31: R34.2 TP9.T@1 TP9.T@2 TP9.T@3 TP9.T@4
N$32: C12.2 IC8.6 R25.2 R28.1
N$33: C12.1 IC8.2 R24.2 R25.1
N$34: J2.CONDUCTOR R21.2 R23.1 R24.1
N$35: C16.2 IC10.3 R28.2 R29.2
N$36: Q3.3 R32.1 TP8.T@1 TP8.T@2 TP8.T@3 TP8.T@4
N$37: Q3.1 R30.1
N$38: Q4.3 R33.1 TP10.T@1 TP10.T@2 TP10.T@3 TP10.T@4
N$39: Q4.1 R35.1
N$40: C27.2 D5.C IC13.3 R40.2 R41.2
N$41: C28.1 IC13.2 R42.1
N$42: C28.2 IC13.6 R43.1 R55.2
N$43: R43.2 TP12.T@1 TP12.T@2 TP12.T@3 TP12.T@4
N$44: D15.A D16.K R53.1
N$45: IC14.1 R45.SENSE2
N$46: IC14.8 R45.SENSE1
N$47: IC14.2 IC14.6
N$48 [Power]: R45.CURRENT2 TP13.T@1 TP13.T@2 TP13.T@3 TP13.T@4
N$49: IC14.5 IC15.3 R44.2 R46.1
N$50: IC15.2 IC15.6 R42.2 R50.2
N$51: C31.1 IC16.2 R50.1
N$52: C31.2 IC16.6 R47.1 R57.2
N$53: R47.2 TP14.T@1 TP14.T@2 TP14.T@3 TP14.T@4
N$54: C33.2 IC17.6 R48.2 R51.1
N$55: C33.1 IC17.2 R48.1 R49.2
N$56: J3.CONDUCTOR R40.1 R49.1 R53.2
N$57: C34.2 IC16.3 R51.2 R52.2
N$58: Q5.3 R54.1 TP15.T@1 TP15.T@2 TP15.T@3 TP15.T@4
N$59: Q5.1 R55.1
N$60: Q6.3 R56.1 TP16.T@1 TP16.T@2 TP16.T@3 TP16.T@4
N$61: Q6.1 R57.1
N$62: C36.2 D6.C IC18.3 R58.2 R59.2
N$63: C37.1 IC18.2 R60.1
N$64: C37.2 IC18.6 R61.1 R73.2
N$65: R61.2 TP17.T@1 TP17.T@2 TP17.T@3 TP17.T@4
N$66: D17.A D18.K R71.1
N$67: IC19.1 R63.SENSE2
N$68: IC19.8 R63.SENSE1
N$69: IC19.2 IC19.6
N$70 [Power]: R63.CURRENT2 TP18.T@1 TP18.T@2 TP18.T@3 TP18.T@4
N$71: IC19.5 IC20.3 R62.2 R64.1
N$72: IC20.2 IC20.6 R60.2 R68.2
N$73: C40.1 IC21.2 R68.1
N$74: C40.2 IC21.6 R65.1 R75.2
N$75: R65.2 TP19.T@1 TP19.T@2 TP19.T@3 TP19.T@4
N$76: C42.2 IC22.6 R66.2 R69.1
N$77: C42.1 IC22.2 R66.1 R67.2
N$78: J4.CONDUCTOR R58.1 R67.1 R71.2
N$79: C43.2 IC21.3 R69.2 R70.2
N$80: Q7.3 R72.1 TP20.T@1 TP20.T@2 TP20.T@3 TP20.T@4
N$81: Q7.1 R73.1
N$82: Q8.3 R74.1 TP21.T@1 TP21.T@2 TP21.T@3 TP21.T@4
N$83: Q8.1 R75.1
N$84: C45.2 D7.C IC23.3 R76.2 R77.2
N$85: C46.1 IC23.2 R78.1
N$86: C46.2 IC23.6 R79.1 R91.2
N$87: R79.2 TP22.T@1 TP22.T@2 TP22.T@3 TP22.T@4
N$88: D19.A D20.K R89.1
N$89: IC24.1 R81.SENSE2
N$90: IC24.8 R81.SENSE1
N$91: IC24.2 IC24.6
N$92 [Power]: R81.CURRENT2 TP23.T@1 TP23.T@2 TP23.T@3 TP23.T@4
N$93: IC24.5 IC25.3 R80.2 R82.1
N$94: IC25.2 IC25.6 R78.2 R86.2
N$95: C49.1 IC26.2 R86.1
N$96: C49.2 IC26.6 R83.1 R93.2
N$97: R83.2 TP24.T@1 TP24.T@2 TP24.T@3 TP24.T@4
N$98: C51.2 IC27.6 R84.2 R87.1
N$99: C51.1 IC27.2 R84.1 R85.2
N$100: J5.CONDUCTOR R76.1 R85.1 R89.2
N$101: C52.2 IC26.3 R87.2 R88.2
N$102: Q9.3 R90.1 TP25.T@1 TP25.T@2 TP25.T@3 TP25.T@4
N$103: Q9.1 R91.1
N$104: Q10.3 R92.1 TP26.T@1 TP26.T@2 TP26.T@3 TP26.T@4
N$105: Q10.1 R93.1
N$110: C4.2 D1.C IC4.3 R5.2 R8.2
N$112: F1.1A P1.9
N$113: D8.A P1.4 R94.2
N$114: C5.1 IC4.2 R9.1
N$115: C5.2 IC4.6 R12.2 R13.1
N$116: HS1.1 HS1.2 P1.1 Q11.2
N$117: R13.2 TP2.T@1 TP2.T@2 TP2.T@3 TP2.T@4
N$118: D8.C D9.C Q11.1 R96.CW R96.W
N$119: D9.A P1.3 R95.2
N$120: D10.3 P1.2 R97.1
N$121: D11.A D12.K R3.1
N$122: J13.CONDUCTOR R98.1 R174.2
N$123: C54.2 D21.C IC28.3 R98.2 R99.2
N$124: IC29.1 R102.SENSE2
N$125: IC29.8 R102.SENSE1
N$126: IC29.2 IC29.6
N$127: C55.1 IC28.2 IC29.5 R100.2 R190.1
N$128: C55.2 IC28.6 R101.1
N$129 [Power]: R102.CURRENT2 TP27.T@1 TP27.T@2 TP27.T@3 TP27.T@4
N$130: R101.2 TP28.T@1 TP28.T@2 TP28.T@3 TP28.T@4
N$131: J11.CONDUCTOR R103.1 R173.2
N$132: C57.2 D22.C IC30.3 R103.2 R104.2
N$133: IC31.1 R107.SENSE2
N$134: IC31.8 R107.SENSE1
N$135: IC31.2 IC31.6
N$136: C58.1 IC30.2 IC31.5 R105.2 R189.1
N$137: C58.2 IC30.6 R106.1
N$138 [Power]: R107.CURRENT2 TP29.T@1 TP29.T@2 TP29.T@3 TP29.T@4
N$139: R106.2 TP30.T@1 TP30.T@2 TP30.T@3 TP30.T@4
N$140: J9.CONDUCTOR R108.1 R171.2
N$141: C60.2 D23.C IC32.3 R108.2 R109.2
N$142: IC33.1 R112.SENSE2
N$143: IC33.8 R112.SENSE1
N$144: IC33.2 IC33.6
N$145: C19.2 D3.2 F1.2A IC11.3
N$146: C20.2 IC11.1 R37.2 R38.1
N$147: C61.1 IC32.2 IC33.5 R110.2 R188.1
N$148: C61.2 IC32.6 R111.1
N$149 [Power]: R112.CURRENT2 TP31.T@1 TP31.T@2 TP31.T@3 TP31.T@4
N$150: R111.2 TP32.T@1 TP32.T@2 TP32.T@3 TP32.T@4
N$151: J12.CONDUCTOR R113.1 R175.2
N$152: C63.2 D24.C IC34.3 R113.2 R114.2
N$153: IC35.1 R117.SENSE2
N$154: IC35.8 R117.SENSE1
N$155: IC35.2 IC35.6
N$156: C64.1 IC34.2 IC35.5 R115.2 R187.1
N$157: C64.2 IC34.6 R116.1
N$158 [Power]: R117.CURRENT2 TP33.T@1 TP33.T@2 TP33.T@3 TP33.T@4
N$159: R116.2 TP34.T@1 TP34.T@2 TP34.T@3 TP34.T@4
N$160: J10.CONDUCTOR R118.1 R172.2
N$161: C66.2 D25.C IC36.3 R118.2 R119.2
N$162: IC37.1 R122.SENSE2
N$163: IC37.8 R122.SENSE1
N$164: IC37.2 IC37.6
N$165: C67.1 IC36.2 IC37.5 R120.2 R186.1
N$166: C67.2 IC36.6 R121.1
N$167 [Power]: R122.CURRENT2 TP35.T@1 TP35.T@2 TP35.T@3 TP35.T@4
N$168: R121.2 TP36.T@1 TP36.T@2 TP36.T@3 TP36.T@4
N$169: J8.CONDUCTOR R123.1 R170.2
N$170: C69.2 D26.C IC38.3 R123.2 R124.2
N$171: IC39.1 R127.SENSE2
N$172: IC39.8 R127.SENSE1
N$173: IC39.2 IC39.6
N$174: C70.1 IC38.2 IC39.5 R125.2 R185.1
N$175: C70.2 IC38.6 R126.1
N$176 [Power]: R127.CURRENT2 TP37.T@1 TP37.T@2 TP37.T@3 TP37.T@4
N$177: R126.2 TP38.T@1 TP38.T@2 TP38.T@3 TP38.T@4
N$178: J6.CONDUCTOR R128.1 R165.2
N$179: C72.2 D27.C IC40.3 R128.2 R129.2
N$180: IC41.1 R132.SENSE2
N$181: IC41.8 R132.SENSE1
N$182: IC41.2 IC41.6
N$183: C73.1 IC40.2 IC41.5 R130.2 R184.1
N$184: C73.2 IC40.6 R131.1
N$185 [Power]: R132.CURRENT2 TP39.T@1 TP39.T@2 TP39.T@3 TP39.T@4
N$186: R131.2 TP40.T@1 TP40.T@2 TP40.T@3 TP40.T@4
N$187: J7.CONDUCTOR R133.1 R168.2
N$188: C75.2 D28.C IC42.3 R133.2 R134.2
N$189: IC43.1 R137.SENSE2
N$190: IC43.8 R137.SENSE1
N$191: IC43.2 IC43.6
N$192: C76.1 IC42.2 IC43.5 R135.2 R183.1
N$193: C76.2 IC42.6 R136.1
N$194 [Power]: R137.CURRENT2 TP41.T@1 TP41.T@2 TP41.T@3 TP41.T@4
N$195: R136.2 TP42.T@1 TP42.T@2 TP42.T@3 TP42.T@4
N$196: J14.CONDUCTOR R138.1 R164.2
N$197: C78.2 D29.C IC44.3 R138.2 R139.2
N$198: IC45.1 R142.SENSE2
N$199: IC45.8 R142.SENSE1
N$200: IC45.2 IC45.6
N$201: C79.1 IC44.2 IC45.5 R140.2 R182.1
N$202: C79.2 IC44.6 R141.1
N$203 [Power]: R142.CURRENT2 TP43.T@1 TP43.T@2 TP43.T@3 TP43.T@4
N$204: R141.2 TP44.T@1 TP44.T@2 TP44.T@3 TP44.T@4
N$205: J15.CONDUCTOR R143.1 R166.2
N$206: C81.2 D30.C IC46.3 R143.2 R144.2
N$207: IC47.1 R147.SENSE2
N$208: IC47.8 R147.SENSE1
N$209: IC47.2 IC47.6
N$210: C82.1 IC46.2 IC47.5 R145.2 R181.1
N$211: C82.2 IC46.6 R146.1
N$212 [Power]: R147.CURRENT2 TP45.T@1 TP45.T@2 TP45.T@3 TP45.T@4
N$213: R146.2 TP46.T@1 TP46.T@2 TP46.T@3 TP46.T@4
N$214: J16.CONDUCTOR R148.1 R169.2
N$215: C84.2 D31.C IC48.3 R148.2 R149.2
N$216: IC49.1 R152.SENSE2
N$217: IC49.8 R152.SENSE1
N$218: IC49.2 IC49.6
N$219: C85.1 IC48.2 IC49.5 R150.2 R180.1
N$220: C85.2 IC48.6 R151.1
N$221 [Power]: R152.CURRENT2 TP47.T@1 TP47.T@2 TP47.T@3 TP47.T@4
N$222: R151.2 TP48.T@1 TP48.T@2 TP48.T@3 TP48.T@4
N$223: J17.CONDUCTOR R153.1 R163.2
N$224: C87.2 D32.C IC50.3 R153.2 R154.2
N$225: IC51.1 R157.SENSE2
N$226: IC51.8 R157.SENSE1
N$227: IC51.2 IC51.6
N$228: C88.1 IC50.2 IC51.5 R155.2 R179.1
N$229: C88.2 IC50.6 R156.1
N$230 [Power]: R157.CURRENT2 TP49.T@1 TP49.T@2 TP49.T@3 TP49.T@4
N$231: R156.2 TP50.T@1 TP50.T@2 TP50.T@3 TP50.T@4
N$232: J18.CONDUCTOR R158.1 R167.2
N$233: C90.2 D33.C IC52.3 R158.2 R159.2
N$234: IC53.1 R162.SENSE2
N$235: IC53.8 R162.SENSE1
N$236: IC53.2 IC53.6
N$237: C91.1 IC52.2 IC53.5 R160.2 R178.1
N$238: C91.2 IC52.6 R161.1
N$239 [Power]: R162.CURRENT2 TP51.T@1 TP51.T@2 TP51.T@3 TP51.T@4
N$240: R161.2 TP52.T@1 TP52.T@2 TP52.T@3 TP52.T@4
N$254: +SUPPLY.TP F2.1A
N$255: C92.2 D34.2 F2.2A IC54.3
N$256: C94.2 IC54.1 R176.1 R177.2
N$257: D35.A R167.1
N$258: D38.A R163.1
N$259: D40.A R169.1
N$260: D36.A R166.1
N$261: D39.A R164.1
N$262: D41.A R168.1
N$263: D37.A R165.1
N$264: D42.A R170.1
N$265: D43.A R171.1
N$266: D45.A R173.1
N$267: D44.A R172.1
N$268: D47.A R175.1
N$269: D46.A R174.1

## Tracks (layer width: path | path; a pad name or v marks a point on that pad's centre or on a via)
+5.0V  (via drill 0.51)
  Top 0.18: v30,84.25 R1.2 | v85,84.25 R19.2 | v140,84.25 R46.2 | R64.2 v195,84.25 | v250,84.25 R82.2 | IC12.6 290.27,85.27 289.5,84.5 285.5,84.5 | 285.5,84.5 285.45,84.5 v285.45,84.4 | 285.5,84.5 C25.2
  Bottom 0.18: v30,84.25 v85,84.25 v140,84.25 v195,84.25 v250,84.25 | v250,84.25 250,84.2 | v250,84.25 250,84.3 285.35,84.3 285.35,84.35 285.5,84.5 285.45,84.5 v285.45,84.4
+5.0V1  (via drill 0.51)
  Top 0.178: R190.2 3.17,202.82 v1.65,202.82 | v26.65,202.82 26.65,202.75 R189.2 | v51.65,202.82 51.65,202.75 R188.2 | v76.65,202.82 76.65,202.75 R187.2 | v101.65,202.82 101.65,202.75 R186.2 | v126.65,202.82 126.65,202.75 R185.2 | v151.65,202.82 151.65,202.75 R184.2 | v176.65,202.82 176.65,202.75 R183.2 | v201.65,202.82 201.65,202.75 R182.2 | v226.65,202.82 226.65,202.75 R181.2 | v251.65,202.82 251.65,202.75 R180.2 | v276.65,202.82 276.65,202.75 R179.2 | v301.65,202.82 301.65,202.75 R178.2
  Top 0.254: 326.14,218.44 C96.2 | IC55.6 330.45,218.44 326.14,218.44 | v325.5,216.03 326.14,216.03 326.14,218.44
  Bottom 0.178: 276.65,203 v276.65,202.82 | v301.65,202.82 301.65,203 276.65,203 | 251.65,203 v251.65,202.82 | 276.65,203 251.65,203 | 226.65,203 v226.65,202.82 | 251.65,203 226.65,203 | 201.65,203 v201.65,202.82 | 226.65,203 201.65,203 | 176.65,203 v176.65,202.82 | 201.65,203 176.65,203 | 151.65,203 v151.65,202.82 | 176.65,203 151.65,203 | 126.65,203 v126.65,202.82 | 151.65,203 126.65,203 | 101.65,203 v101.65,202.82 | 126.65,203 101.65,203 | 76.65,203 v76.65,202.82 | 101.65,203 76.65,203 | 51.65,203 v51.65,202.82 | 76.65,203 51.65,203 | 26.65,203 v26.65,202.82 | 51.65,203 26.65,203 | 1.65,203 1.5,203 | 1.65,203 v1.65,202.82 | 26.65,203 1.65,203
  Bottom 0.254: v325.5,216.03 325.5,202.95 301.62,202.95 301.62,203 301.65,203
+10V  (via drill 0.51)
  Top 0.18: R14.2 6,83.5 7.75,85.25 v8.5,85.25 | R32.2 61,83.5 62.75,85.25 v63.5,85.25 | v45,85.25 R15.2 | v100,85.25 R33.2 | R54.2 116,83.5 117.75,85.25 v118.5,85.25 | v155,85.25 R56.2 | R72.2 171,83.5 172.75,85.25 v173.5,85.25 | v210,85.25 R74.2 | R90.2 226,83.5 227.75,85.25 v228.5,85.25 | v265,85.25 R92.2 | C23.2 273,88.5 273.58,89.08 | R39.2 282.5,81.5 275.8,88.2 275.8,89.08
  Top 0.36: 273.58,89.08 275.8,89.08 275.75,89.25 277.75,91.25 278.75,91.25 279,91 D4.2 | C23.2 C22.2
  Bottom 0.18: v8.5,85.25 v45,85.25 v63.5,85.25 v100,85.25 v118.5,85.25 v155,85.25 v173.5,85.25 v210,85.25 v228.5,85.25 v265,85.25 271,91.25 278.75,91.25 279,91 279,89 D4.2
+16V  (via drill 0.71)
  Top 0.178: C53.1 22.05,205.39 22.05,205.33 21.92,205.46 IC28.7 | C56.1 47.05,205.39 47.05,205.33 46.92,205.46 IC30.7 | C59.1 72.05,205.39 72.05,205.33 71.92,205.46 IC32.7 | C62.1 97.05,205.39 97.05,205.33 96.92,205.46 IC34.7 | C65.1 122.05,205.39 122.05,205.33 121.92,205.46 IC36.7 | C68.1 147.05,205.39 147.05,205.33 146.92,205.46 IC38.7 | C71.1 172.05,205.39 172.05,205.33 171.92,205.46 IC40.7 | C74.1 197.05,205.39 197.05,205.33 196.92,205.46 IC42.7 | C77.1 222.05,205.39 222.05,205.33 221.92,205.46 IC44.7 | C80.1 247.05,205.39 247.05,205.33 246.92,205.46 IC46.7 | C83.1 272.05,205.39 272.05,205.33 271.92,205.46 IC48.7 | C86.1 297.05,205.39 297.05,205.33 296.92,205.46 IC50.7 | C89.1 322.05,205.39 322.05,205.33 321.92,205.46 IC52.7
  Top 0.254: 329.18,213.42 329.18,213.36 | 329.18,213.42 C95.1 329.27,204.6 329.31,204.6 | 329.18,213.42 IC55.2
  Top 0.381: 22.05,205.39 24,205.39 v24,205.5 | v49,205.39 47.05,205.39 | 72.05,205.39 74,205.39 v74,205.5 | 97.05,205.39 99,205.39 v99,205.5 | 122.05,205.39 124,205.39 v124,205.5 | 147.05,205.39 149,205.39 v149,205.5 | 172.05,205.39 174,205.39 v174,205.5 | 197.05,205.39 199,205.39 v199,205.5 | 222.05,205.39 224,205.39 v224,205.5 | 247.05,205.39 249,205.39 v249,205.5 | 272.05,205.39 274,205.39 v274,205.5 | 297.05,205.39 299,205.39 v299,205.5 | 322.05,205.39 324,205.39 | 324,205.39 v324,205.5 | IC54.2 341.82,205.11 R176.2 341.5,203.07 | 341.5,203.07 341.5,201.04 C93.2 | 324,205.39 324.8,204.6 329.31,204.6 336.23,204.6 337.76,203.07 341.5,203.07 | 341.5,203.07 341.57,203.07
  Bottom 0.254: 49,205.37 v49,205.38 v49,205.39
  Bottom 0.381: 49,205.37 v24,205.5 | 74,205.39 v49,205.39 | 74,205.39 v74,205.5 | 99,205.39 74,205.39 | 99,205.39 v99,205.5 | 124,205.39 99,205.39 | 124,205.39 v124,205.5 | 149,205.39 124,205.39 | 149,205.39 v149,205.5 | 174,205.39 149,205.39 | 174,205.39 v174,205.5 | 199,205.39 174,205.39 | 199,205.39 v199,205.5 | 224,205.39 199,205.39 | 224,205.39 v224,205.5 | 249,205.39 224,205.39 | 249,205.39 v249,205.5 | 274,205.39 249,205.39 | 274,205.39 v274,205.5 | 299,205.39 274,205.39 | 299,205.39 v299,205.5 | 299,205.39 324,205.39 v324,205.5
  pour Top (isolate 0.508): 335.47,226.14 335.47,211.71 348.17,211.71 348.17,226.14
+16V1  (via drill 0.51)
  Top 0.18: IC4.7 8,91 8.1,90.9 C6.1 7.9,90.9 9.9,90.9 10.9,89.9 | IC2.7 17.1,87 17,86.9 C1.1 13.85,86.95 10.9,89.9 | 23,93 22.9,93 22.9,93.05 C2.1 23,93 | 23,93 IC3.7 | 46,93.5 IC5.7 C8.1 | 10.9,89.9 10.9,90 11,90 v12,91 | v19,91 21,93 23,93 | IC9.7 63,91 63.1,90.9 C15.1 62.9,90.9 64.9,90.9 65.9,89.9 | IC7.7 72.1,87 72,86.9 C10.1 68.85,86.95 65.9,89.9 | 78,93 77.9,93 77.9,93.05 C11.1 78,93 | 78,93 IC8.7 | 101,93.5 IC10.7 C17.1 | 65.9,89.9 65.9,90 66,90 v67,91 | v74,91 76,93 78,93 | IC13.7 118,91 118.1,90.9 C26.1 117.9,90.9 119.9,90.9 120.9,89.9 | IC15.7 127.1,87 127,86.9 C29.1 123.85,86.95 120.9,89.9 | 133,93 132.9,93 132.9,93.05 C32.1 133,93 | 133,93 IC17.7 | 156,93.5 IC16.7 C30.1 | 120.9,89.9 120.9,90 121,90 v122,91 | v129,91 131,93 133,93 | IC18.7 173,91 173.1,90.9 C35.1 172.9,90.9 174.9,90.9 175.9,89.9 | IC20.7 182.1,87 182,86.9 C38.1 178.85,86.95 175.9,89.9 | 188,93 187.9,93 187.9,93.05 C41.1 188,93 | 188,93 IC22.7 | 211,93.5 IC21.7 C39.1 | 175.9,89.9 175.9,90 176,90 v177,91 | v184,91 186,93 188,93 | IC23.7 228,91 228.1,90.9 C44.1 227.9,90.9 229.9,90.9 230.9,89.9 | IC25.7 237.1,87 237,86.9 C47.1 233.85,86.95 230.9,89.9 | 243,93 242.9,93 242.9,93.05 C50.1 243,93 | 243,93 IC27.7 | 266,93.5 IC26.7 C48.1 | 230.9,89.9 230.9,90 231,90 v232,91 | v239,91 241,93 243,93 | v268,91 269,91 272,94 272.4,94 C21.2 | 285.5,81.5 R39.1 | C24.1 285.45,81.45 285.5,81.5 | 285.5,82 285.5,81.5 | 285.5,82 287,83.5 289,83.5 | 289,83.5 IC12.2 | R38.2 277,106.75 276.75,107 IC11.2 272.8,107 v271.7,105.9 | R97.2 293.5,83.55 293.5,83.5 289,83.5 | C21.2 | C21.2 273,94.75 | 285.5,82 281.2,86.3 v281.2,92.3
  Top 0.36: C8.1 47.95,90.95 v48,91 | C17.1 102.95,90.95 v103,91 | C30.1 157.95,90.95 v158,91 | C39.1 212.95,90.95 v213,91 | C48.1 267.95,90.95 v268,91
  Bottom 0.18: v12,91 v19,91 v48,91 v67,91 v74,91 v103,91 v122,91 v129,91 v158,91 v177,91 v184,91 v213,91 v232,91 v239,91 v268,91 268.1,91 269.4,92.3 | v271.7,105.9 271.7,94.6 269.4,92.3 | 269.4,92.3 v281.2,92.3
  pour Top: 257,101 270,101 270,113 257,113
+V-COIL  (via drill 3.86)
  Top 2: 5,184.4 5,184.3 5.2,179.1
  Top 7.62: R102.CURRENT1 v5.2,184.2 5.2,179.1 v5.2,177.8 5,178 30,178 | 55,178 30,178 | 80,178 55,178 | 80,178 105,178 | 105,178 130,178 | 130,178 155,178 | 155,178 180,178 | 180,178 205,178 | 205,178 230,178 | 230,178 255,178 | 255,178 280,178 | 280,178 305,178 v305.2,177.8 v305.2,184.2 R162.CURRENT1 | 30,178 v30.2,177.8 v30.2,184.2 R107.CURRENT1 | 55,178 v55.2,177.8 v55.2,184.2 R112.CURRENT1 | 80,178 v80.2,177.8 v80.2,184.2 R117.CURRENT1 | 105,178 v105.2,177.8 v105.2,184.2 R122.CURRENT1 | 130,178 v130.2,177.8 v130.2,184.2 R127.CURRENT1 | 155,178 v155.2,177.8 v155.2,184.2 R132.CURRENT1 | 180,178 v180.2,177.8 v180.2,184.2 R137.CURRENT1 | 205,178 v205.2,177.8 v205.2,184.2 R142.CURRENT1 | 230,178 v230.2,177.8 v230.2,184.2 R147.CURRENT1 | 255,178 v255.2,177.8 v255.2,184.2 R152.CURRENT1 | 280,178 v280.2,177.8 v280.2,184.2 R157.CURRENT1 | 5,184.4 305,184.4
  Bottom 7.62: v5.2,177.8 v5.2,184.2 R102.CURRENT1 | R107.CURRENT1 v30.2,184.2 v30.2,177.8 | R112.CURRENT1 v55.2,184.2 v55.2,177.8 | R117.CURRENT1 v80.2,184.2 v80.2,177.8 | R122.CURRENT1 v105.2,184.2 v105.2,177.8 | R127.CURRENT1 v130.2,184.2 v130.2,177.8 | R132.CURRENT1 v155.2,184.2 v155.2,177.8 | R137.CURRENT1 v180.2,184.2 v180.2,177.8 | R142.CURRENT1 v205.2,184.2 v205.2,177.8 | R147.CURRENT1 v230.2,184.2 v230.2,177.8 | R152.CURRENT1 v255.2,184.2 v255.2,177.8 | R157.CURRENT1 v280.2,184.2 v280.2,177.8 | R162.CURRENT1 v305.2,184.2 v305.2,177.8
+V-COIL1  (via drill 3.86)
  Top 2: R4.CURRENT1 | R22.CURRENT1 | R45.CURRENT1 | R63.CURRENT1 | R81.CURRENT1
  Top 7.5: v25.2,69.2 R4.CURRENT1 | v25.2,69.2 v25.2,62.8 v80.2,62.8 | v80.2,69.2 R22.CURRENT1 | v80.2,69.2 v80.2,62.8 | v80.2,69.2 v25.2,69.2 | v135.2,69.2 R45.CURRENT1 | v135.2,69.2 v135.2,62.8 | v135.2,69.2 v80.2,69.2 | v135.2,62.8 v80.2,62.8 | v190.2,69.2 R63.CURRENT1 | v190.2,69.2 v190.2,62.8 | v190.2,69.2 v135.2,69.2 | v190.2,62.8 v135.2,62.8 | v245.2,69.2 R81.CURRENT1 | v245.2,69.2 v245.2,62.8 | v190.2,69.2 v245.2,69.2 | v190.2,62.8 v245.2,62.8 | v245.2,62.8 283.2,62.8 283.2,69.2 v245.2,69.2
  Bottom 7.5: R4.CURRENT1 v25.2,69.2 v25.2,62.8 | R22.CURRENT1 v80.2,69.2 v80.2,62.8 | R45.CURRENT1 v135.2,69.2 v135.2,62.8 | R63.CURRENT1 v190.2,69.2 v190.2,62.8 | R81.CURRENT1 v245.2,69.2 v245.2,62.8
AGND  (via drill 0.71)
  Top 0.36: C92.1 347.44,204.56 SUPPY_RET.TP
  Bottom 0.18: J13.SHIELD1 14.03,218.5 14,218.5 16.2,220.7 D46.K | J11.SHIELD1 39.03,218.5 39,218.5 41.2,220.7 D45.K | J9.SHIELD1 64.03,218.5 64,218.5 66.2,220.7 D43.K | J12.SHIELD1 89.03,218.5 89,218.5 91.2,220.7 D47.K | J10.SHIELD1 114.03,218.5 114,218.5 116.2,220.7 D44.K | J8.SHIELD1 139.03,218.5 139,218.5 141.2,220.7 D42.K | J6.SHIELD1 164.03,218.5 164,218.5 166.2,220.7 D37.K | J7.SHIELD1 189.03,218.5 189,218.5 191.2,220.7 D41.K | J14.SHIELD1 214.03,218.5 214,218.5 216.2,220.7 D39.K | J15.SHIELD1 239.03,218.5 239,218.5 241.2,220.7 D36.K | J16.SHIELD1 264.03,218.5 264,218.5 266.2,220.7 D40.K | J17.SHIELD1 289.03,218.5 289,218.5 291.2,220.7 D38.K | J18.SHIELD1 314.03,218.5 314,218.5 316.2,220.7 D35.K
  Bottom 0.381: TP53.T@4 325.12,152.18 325.12,196.47 v323.85,197.74
  Bottom 2.54: TP53.T@1 331.85,134.11 TP53.T@2 331.85,149.23 TP53.T@3 328.17,149.23 TP53.T@4
  pour Top (isolate 0.178, rank 2): 0,227 0,196 349,196 349,227
AGND1  (via drill 0.71)
  Top 0.5: P1.5 305.08,92.08 304.5,91.5
  Bottom 0.18: v293.62,91.82 293.6,91.8 | D11.K 40.7,107.3 40.75,107.25 40.75,107.3 D12.A 29.8,107.3 27.5,105 J1.SHIELD1 | D13.K 93,107.25 93.05,107.3 D14.A 84.8,107.3 82.5,105 J2.SHIELD1 | D15.K 150.95,107.3 151,107.25 D16.A 139.8,107.3 137.5,105 J3.SHIELD1 | D17.K 205.95,107.3 206,107.25 D18.A 194.8,107.3 192.5,105 J4.SHIELD1 | D19.K 260.95,107.3 261,107.25 D20.A 249.8,107.3 247.5,105 J5.SHIELD1
  Bottom 0.4: D4.1 279,77 278,76 274,76 273,75 273,74
  Bottom 0.406: TP11.T@4 278.1,44.5 273,44.5 273,74
  Bottom 1: 293.6,91.8 293.6,95
  Bottom 2: TP11.T@1 TP11.T@2 TP11.T@3 TP11.T@4
  pour Top (rank 2): 305,114 305,76 0,76 0,114
N$1
  Top 0.18: IC2.3 27.63,88.27 28,87.9 R2.2 29.95,87.95 30,87.9 R1.1 32.45,87.95 IC1.5
N$2
  Top 0.18: R9.2 14,92.5 18.23,88.27 IC2.6 19.4,88.27 19.3,88.2 21.4,88.2 21.55,88.05 | IC2.2 22.6,87 21.55,88.05 | R18.2 41.45,95.05 42.5,94 42.5,90 42,89.5 27.5,89.5 26.5,90.5 22.5,90.5 21.5,89.5 21.5,88 21.55,88 21.55,88.05
N$3  (via drill 0.51)
  Top 0.18: IC1.1 37.05,86 37,86 v37,77
  Bottom 0.36: R4.SENSE2 33.3,53.3 37,57 v37,77
N$4
  Top 0.36: R4.SENSE1 31.54,78.5 31.5,78.5 32.61,79.61 IC1.8
N$5
  Top 0.18: IC1.2 35.16,86.54 34.6,87.1 32.8,87.1 32.7,87.17 IC1.6
N$6
  Top 0.18: 34,96.9 R6.1 34,103.05 26.95,103.05 J1.CONDUCTOR 22.95,102.95 R5.1
  Bottom 0.18: R3.2 34.7,104.95 33,103.25 26.75,103.25 J1.CONDUCTOR
N$7
  Top 0.18: 46,97.3 IC5.2 | 46,97.3 46.4,96.9 49.9,96.9 50,97 C9.1 | R18.1 45.65,96.95 46,97.3
N$8
  Top 4: TP1.T@1 TP1.T@4 25.2,34.5 | TP1.T@2 TP1.T@3 25.2,34.5 | 25.2,34.5 25.19,34.5
  Top 7.6: 25.19,34.5 R4.CURRENT2
  Bottom 4: TP1.T@1 TP1.T@4 | TP1.T@3 TP1.T@2
  Bottom 7.6: R4.CURRENT2 25.19,34.5
N$9
  Top 0.18: C9.2 50,95 49.9,95.1 45,95.1 44.73,94.83 IC5.6 44.73,87.23 | 44.73,87.23 44.73,87 R17.2 | 44.73,87.23 42,84.5 R16.1
N$10  (via drill 0.51)
  Top 0.18: v42,77 R16.2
